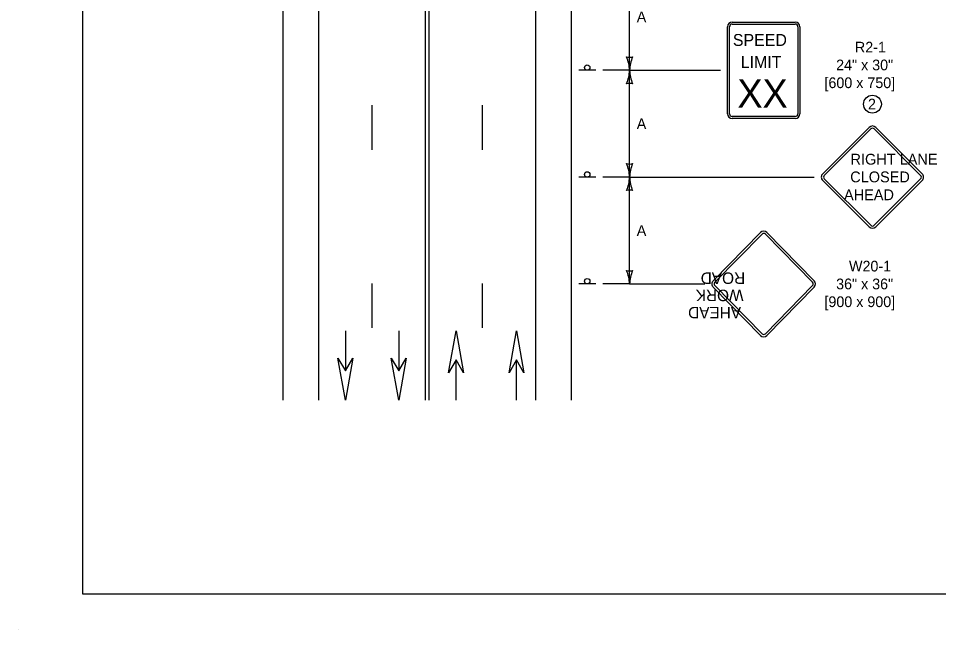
# Model space of a CAD drawing. Extents: x 49991.4 to 50021, y 49987.6 to 50011.4.
# Drawn here: x 49999.98 to 50005.14, y 49999.86 to 50003.3 of the extents above; entities that cross this region are included whole.
import ezdxf

# ---------------------------------------------------------------- set-up
doc = ezdxf.new("R2010")
doc.units = 0
for name, color, linetype in [('Level 1', 7, 'Continuous'), ('Level 2', 7, 'Continuous'), ('Level 3', 7, 'Continuous')]:
    doc.layers.add(name, color=color, linetype=linetype)

msp = doc.modelspace()

# ---------------------------------------------------------------- linework, layer by layer
at = {"layer": 'Level 1'}
for p, q in [((50001.4626, 50001.1514), (50001.4626, 50009.2134)), ((50001.6625, 50001.1514), (50001.6625, 50009.2134)), ((50002.2625, 50001.1514), (50002.2625, 50009.2134)), ((50002.2825, 50001.1514), (50002.2825, 50009.2134)), ((50003.0824, 50001.1514), (50003.0824, 50009.2134)), ((50002.8825, 50001.1514), (50002.8825, 50005.2541)), ((50003.9839, 50003.2741), (50004.3383, 50003.2741)), ((50004.1611, 50003.2741), (50004.1611, 50003.2741)), ((50003.9586, 50002.7594), (50003.9586, 50003.2488)), ((50003.9691, 50002.7594), (50003.9691, 50003.2488)), ((50003.9839, 50003.2636), (50004.3383, 50003.2636)), ((50004.3531, 50003.2488), (50004.3531, 50002.7594)), ((50004.3636, 50003.2488), (50004.3636, 50002.7594)), ((50003.2184, 50003.0041), (50003.1224, 50003.0041)), ((50001.9626, 50002.5574), (50001.9626, 50002.8074)), ((50001.9626, 50002.5574), (50001.9626, 50002.8074)), ((50002.5826, 50002.5574), (50002.5826, 50002.8074)), ((50002.5826, 50002.5574), (50002.5826, 50002.8074)), ((50004.3383, 50002.7446), (50003.9839, 50002.7446)), ((50004.3383, 50002.734), (50003.9839, 50002.734)), ((50004.7531, 50002.6835), (50004.4923, 50002.4227)), ((50004.7619, 50002.6747), (50004.5011, 50002.4139)), ((50004.7531, 50002.6835), (50004.7531, 50002.6835)), ((50004.7619, 50002.6747), (50004.7619, 50002.6747)), ((50005.0423, 50002.4139), (50004.7815, 50002.6747)), ((50005.0511, 50002.4227), (50004.7903, 50002.6835)), ((50003.2184, 50002.4041), (50003.1224, 50002.4041)), ((50004.5011, 50002.3942), (50004.7619, 50002.1335)), ((50004.7717, 50002.4041), (50004.7717, 50002.4041)), ((50004.7717, 50002.4041), (50004.7717, 50002.4041)), ((50004.7717, 50002.4041), (50004.7717, 50002.4041)), ((50004.7815, 50002.1335), (50005.0423, 50002.3942)), ((50004.4923, 50002.3855), (50004.7531, 50002.1247)), ((50004.7903, 50002.1247), (50005.0511, 50002.3855)), ((50003.8778, 50001.8222), (50004.143, 50002.0929)), ((50003.8866, 50001.8136), (50004.1518, 50002.0843)), ((50004.1704, 50002.0843), (50004.4356, 50001.8136)), ((50004.1793, 50002.0929), (50004.4444, 50001.8222)), ((50001.9626, 50001.5574), (50001.9626, 50001.8074)), ((50001.9626, 50001.5574), (50001.9626, 50001.8074)), ((50002.5826, 50001.5574), (50002.5826, 50001.8074)), ((50002.5826, 50001.5574), (50002.5826, 50001.8074)), ((50003.2184, 50001.8041), (50003.1224, 50001.8041)), ((50004.143, 50001.5153), (50003.8778, 50001.786)), ((50004.1518, 50001.524), (50003.8866, 50001.7947)), ((50004.4356, 50001.7947), (50004.1704, 50001.524)), ((50004.4444, 50001.786), (50004.1793, 50001.5153)), ((50001.8124, 50001.5415), (50001.8124, 50001.3156)), ((50001.8128, 50001.5415), (50001.8128, 50001.3156)), ((50002.1118, 50001.5415), (50002.1118, 50001.3156)), ((50002.1122, 50001.5415), (50002.1122, 50001.3156)), ((50002.4341, 50001.1514), (50002.4341, 50001.3773)), ((50002.4343, 50001.1514), (50002.4343, 50001.3773)), ((50002.7735, 50001.1513), (50002.7735, 50001.3772)), ((50002.7737, 50001.1513), (50002.7737, 50001.3772)), ((49999.9766, 49999.8624), (49999.9766, 49999.8624))]:
    msp.add_line(p, q, dxfattribs=at)
for points in [[(50008.6146, 50011.2628), (50000.3356, 50011.2628), (50000.3356, 50000.0624), (50008.6146, 50000.0624)], [(50002.3923, 50001.305), (50002.4341, 50001.5415), (50002.4759, 50001.305), (50002.4341, 50001.3772)], [(50002.7317, 50001.3049), (50002.7735, 50001.5414), (50002.8153, 50001.3049), (50002.7735, 50001.3771)], [(50001.8544, 50001.3879), (50001.8128, 50001.1514), (50001.7708, 50001.3879), (50001.8128, 50001.3157)], [(50002.1538, 50001.3879), (50002.1122, 50001.1514), (50002.0702, 50001.3879), (50002.1122, 50001.3157)]]:
    msp.add_lwpolyline(points, close=True, dxfattribs=at)
for centre in [(50003.1704, 50003.0192), (50003.1704, 50002.4192), (50003.1704, 50001.8192)]:
    msp.add_circle(centre, 0.0152, dxfattribs=at)
for centre, radius, start, end in [((50003.9839, 50003.2488), 0.0253, 90, 180), ((50004.3383, 50003.2488), 0.0253, 0, 90), ((50003.9839, 50003.2488), 0.0148, 90, 180), ((50004.3383, 50003.2488), 0.0148, 0, 90), ((50003.9839, 50002.7594), 0.0253, 180, 270), ((50003.9839, 50002.7594), 0.0148, 180, 270), ((50004.3383, 50002.7594), 0.0148, 270, 360), ((50004.3383, 50002.7594), 0.0253, 270, 360), ((50004.7717, 50002.6649), 0.0263, 45.0001, 134.9999), ((50004.7717, 50002.6649), 0.0139, 45.0001, 134.9999), ((50004.5109, 50002.4041), 0.0263, 134.9999, 225.0001), ((50004.5109, 50002.4041), 0.0139, 134.9999, 225.0001), ((50005.0325, 50002.4041), 0.0139, 314.9999, 45.0001), ((50005.0325, 50002.4041), 0.0263, 314.9999, 45.0001), ((50004.7717, 50002.1433), 0.0139, 225.0001, 314.9999), ((50004.7717, 50002.1433), 0.0263, 225.0001, 314.9999)]:
    msp.add_arc(centre, radius, start, end, dxfattribs=at)
for centre, major_axis, ratio, start_param, end_param in [((50004.1611, 50002.0747), (0, 0.0258), 0.98963, 5.497787, 7.068583), ((50004.1611, 50002.0747), (0, 0.0134), 0.98, 5.497787, 7.068583), ((50003.8959, 50001.8041), (0, 0.0258), 0.98963, 0.785394, 2.356194), ((50004.4263, 50001.8041), (0, 0.0258), 0.98963, 3.926991, 5.497787), ((50003.8959, 50001.8041), (0, 0.0134), 0.98, 0.785394, 2.356194), ((50004.4263, 50001.8041), (0, 0.0134), 0.98, 3.926991, 5.497787), ((50004.1611, 50001.5334), (0, -0.0258), 0.98963, 5.497795, 7.068583), ((50004.1611, 50001.5334), (0, -0.0134), 0.98, 5.497795, 7.068583)]:
    msp.add_ellipse(centre, major_axis=major_axis, ratio=ratio, start_param=start_param, end_param=end_param, dxfattribs=at)
at = {"layer": 'Level 2'}
msp.add_circle((50004.7716, 50002.814), 0.0501, dxfattribs=at)
at = {"layer": 'Level 3'}
for p, q in [((50003.4084, 50003.0041), (50003.4084, 50003.6041)), ((50003.4084, 50003.0041), (50003.2584, 50003.0041)), ((50003.4084, 50003.0041), (50003.5084, 50003.0041)), ((50003.4084, 50002.4041), (50003.4084, 50003.0041)), ((50003.5084, 50003.0041), (50003.9186, 50003.0041)), ((50003.4084, 50002.4041), (50003.2584, 50002.4041)), ((50003.4084, 50002.4041), (50003.5084, 50002.4041)), ((50003.4084, 50001.8041), (50003.4084, 50002.4041)), ((50003.5084, 50002.4041), (50004.4446, 50002.4041)), ((50003.4084, 50001.8041), (50003.2584, 50001.8041)), ((50003.4084, 50001.8041), (50003.5084, 50001.8041)), ((50003.5084, 50001.8041), (50003.8304, 50001.8041))]:
    msp.add_line(p, q, dxfattribs=at)
for centre, radius, start, end in [((50003.4084, 50003.1323), 0.0548, 252.1388, 287.8612), ((50003.1757, 50002.9926), 0.233, 2.8273, 22.0772), ((50003.6305, 50002.9949), 0.2223, 157.456, 177.6395), ((50003.1863, 50003.0132), 0.2223, 337.456, 357.6395), ((50003.6411, 50003.0156), 0.233, 182.8273, 202.0772), ((50003.4084, 50002.8759), 0.0548, 72.1388, 107.8612), ((50003.4084, 50002.5323), 0.0548, 252.1388, 287.8612), ((50003.1757, 50002.3926), 0.233, 2.8273, 22.0772), ((50003.6305, 50002.3949), 0.2223, 157.456, 177.6395), ((50003.1863, 50002.4132), 0.2223, 337.456, 357.6395), ((50003.6411, 50002.4156), 0.233, 182.8273, 202.0772), ((50003.4084, 50002.2759), 0.0548, 72.1388, 107.8612), ((50003.4084, 50001.9323), 0.0548, 252.1388, 287.8612), ((50003.1757, 50001.7926), 0.233, 2.8273, 22.0772), ((50003.6305, 50001.7949), 0.2223, 157.456, 177.6395)]:
    msp.add_arc(centre, radius, start, end, dxfattribs=at)

# ---------------------------------------------------------------- texts
at = {"layer": 'Level 1'}
for s, height, p in [('SPEED', 0.06695, (50003.988, 50003.1409)), ('LIMIT', 0.06695, (50004.0323, 50003.0171)), ('XX', 0.15772, (50004.014, 50002.7951)), ('RIGHT LANE', 0.06088, (50004.6486, 50002.4742)), ('CLOSED', 0.06088, (50004.6469, 50002.3748)), ('  AHEAD', 0.06088, (50004.5668, 50002.2744))]:
    msp.add_text(s, height=height, dxfattribs=at).set_placement(p)
for s, p in [('ROAD', (50004.0569, 50001.8686)), ('WORK', (50004.0479, 50001.7719)), ('AHEAD', (50004.0341, 50001.6751))]:
    msp.add_text(s, height=0.06453, rotation=180, dxfattribs=at).set_placement(p)
at = {"layer": 'Level 2'}
for p in [(50003.4484, 50003.2741), (50003.4484, 50002.6741), (50003.4484, 50002.0741)]:
    msp.add_text('A', height=0.06, rotation=360, dxfattribs=at).set_placement(p)
for s, p in [('R2-1', (50004.6734, 50003.1041)), ('24" x 30"', (50004.5679, 50003.0041)), ('[600 x 750]', (50004.5023, 50002.9041)), ('2', (50004.7466, 50002.7841)), ('W20-1', (50004.6401, 50001.8741)), ('36" x 36"', (50004.5679, 50001.7741)), ('[900 x 900]', (50004.5023, 50001.6741))]:
    msp.add_text(s, height=0.06, dxfattribs=at).set_placement(p)

doc.saveas('drawing.dxf')
